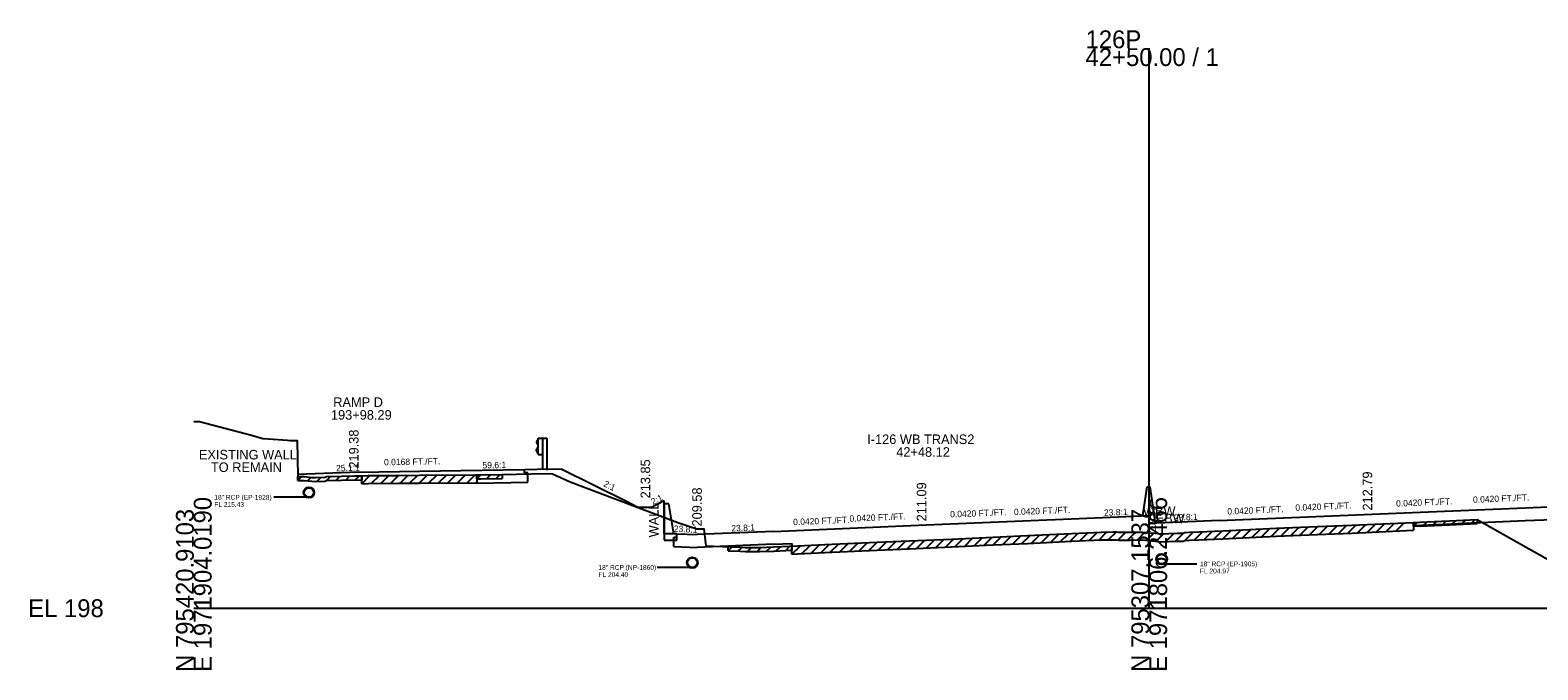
# Model space of a CAD drawing. Extents: x -161 to 1970889, y -4362 to 797231.
# Drawn here: x 974.3 to 1211, y 4990.3 to 5090.9 of the extents above; entities that cross this region are included whole.
import ezdxf

# ---------------------------------------------------------------- set-up
doc = ezdxf.new("R2010")
doc.units = 0
for name, color, linetype in [('RD_GPK_XS_Cell', 7, 'Continuous'), ('RD_XS_Base', 7, 'Continuous'), ('RD_XS_Box', 7, 'Continuous'), ('RD_XS_EarthShd', 7, 'Continuous'), ('RD_XS_ExGround', 7, 'Continuous'), ('RD_XS_ExPaveRet', 7, 'Continuous'), ('RD_XS_GR', 7, 'Continuous'), ('RD_XS_MedBWall', 7, 'Continuous'), ('RD_XS_Misc_Line', 7, 'Continuous'), ('RD_XS_Pave', 7, 'Continuous'), ('RD_XS_PaveOvlay', 7, 'Continuous'), ('RD_XS_PaveShd', 7, 'Continuous'), ('RD_XS_Pipe', 7, 'Continuous'), ('RD_XS_TieSlope', 7, 'Continuous'), ('RD_XS_TX_Elev_EX', 7, 'Continuous'), ('RD_XS_TX_Elev_PR', 7, 'Continuous'), ('RD_XS_TX_Misc', 7, 'Continuous'), ('RD_XS_TX_MkPT', 7, 'Continuous'), ('RD_XS_TX_Notes', 7, 'Continuous'), ('RD_XS_TX_Profile', 7, 'Continuous'), ('RD_XS_TX_Slope', 7, 'Continuous'), ('RD_XS_TX_Station', 7, 'Continuous')]:
    doc.layers.add(name, color=color, linetype=linetype)

msp = doc.modelspace()

# ---------------------------------------------------------------- linework, layer by layer
at = {"layer": 'RD_GPK_XS_Cell'}
for p, q in [((1150, 5000), (1150, 5088.01)), ((1000, 5000), (1150, 5000)), ((1150, 5000), (1300, 5000))]:
    msp.add_line(p, q, dxfattribs=at)
at = {"layer": 'RD_XS_Base'}
for p, q in [((1051.92, 5021.26), (1051.92, 5021.82)), ((1052.42, 5021.27), (1051.92, 5021.26)), ((1052.42, 5019.79), (1052.42, 5021.27)), ((1044.42, 5019.66), (1052.42, 5019.79)), ((1191.46, 5013.02), (1209, 5013.76)), ((1209, 5013.76), (1226.81, 5014.51)), ((1075.34, 5011.17), (1075.84, 5011.15)), ((1075.34, 5009.69), (1075.34, 5011.17)), ((1075.84, 5011.15), (1075.84, 5011.71)), ((1075.84, 5010.88), (1075.84, 5011.44)), ((1075.34, 5009.69), (1079, 5009.54)), ((1091, 5010.04), (1079, 5009.54)), ((1091, 5010.04), (1093.91, 5010.16))]:
    msp.add_line(p, q, dxfattribs=at)
at = {"layer": 'RD_XS_Box'}
for p, q in [((1073.84, 5011.71), (1073.84, 5016.85)), ((1075.84, 5011.71), (1073.84, 5011.71))]:
    msp.add_line(p, q, dxfattribs=at)
at = {"layer": 'RD_XS_EarthShd'}
msp.add_line((1051.92, 5021.82), (1053.92, 5021.85), dxfattribs=at)
at = {"layer": 'RD_XS_ExGround'}
msp.add_lwpolyline([(1000, 5029.34), (1000.89, 5029.32), (1009.06, 5027.22), (1010.83, 5026.67), (1011.72, 5026.61), (1014.7, 5026.39), (1015.05, 5026.36), (1016.23, 5026.36), (1016.33, 5020.71), (1017.35, 5020.68), (1018.54, 5020.56), (1019.1, 5020.52), (1020.57, 5020.6), (1020.84, 5020.71), (1023.18, 5020.75), (1027.35, 5020.83), (1032.16, 5020.88), (1035.44, 5020.92), (1044.22, 5020.94), (1044.53, 5020.95), (1045.07, 5020.95), (1048.43, 5020.99), (1050.65, 5021.04), (1055.38, 5021.15), (1056.3, 5021.14), (1059.11, 5019.86), (1076, 5013.48), (1078.98, 5012.47), (1079.42, 5012.47), (1080.05, 5012.47), (1080.38, 5009.8), (1081.6, 5009.75), (1085.79, 5009.57), (1086.56, 5009.53), (1087.24, 5009.54), (1088.79, 5009.55), (1091.05, 5009.62), (1094.82, 5009.79), (1099.05, 5010), (1107.21, 5010.38), (1112.31, 5010.59), (1118.93, 5010.87), (1125.49, 5011.19), (1130.89, 5011.44), (1137.81, 5011.76), (1142.47, 5011.97), (1144.31, 5011.99), (1144.85, 5012), (1145.18, 5011.93), (1146.94, 5011.95), (1148.94, 5011.97), (1150, 5011.87), (1150.96, 5011.79), (1151.71, 5011.7), (1154.4, 5011.77), (1155.35, 5011.78), (1155.59, 5011.91), (1156.34, 5011.95), (1157.77, 5012.01), (1161.5, 5012.17), (1169.96, 5012.56), (1176.35, 5012.82), (1181.79, 5013.05), (1191.43, 5013.49), (1193.57, 5013.59), (1197.14, 5013.74), (1201.46, 5013.93), (1209.2, 5009.59), (1223.35, 5001.64)], dxfattribs=at)
at = {"layer": 'RD_XS_ExPaveRet'}
for p, q in [((1016.33, 5020.08), (1016.33, 5020.71)), ((1026.36, 5019.56), (1026.36, 5020.81)), ((1026.36, 5020.81), (1026.36, 5020.19)), ((1044.42, 5020.95), (1044.42, 5019.7)), ((1044.42, 5020.32), (1044.42, 5020.95)), ((1048.43, 5020.99), (1048.43, 5020.36)), ((1016.33, 5020.08), (1017.35, 5020.06)), ((1017.35, 5020.06), (1018.54, 5019.94)), ((1018.54, 5019.94), (1019.1, 5019.89)), ((1019.1, 5019.89), (1020.57, 5019.97)), ((1020.57, 5019.97), (1020.84, 5020.08)), ((1020.84, 5020.08), (1023.18, 5020.12)), ((1023.18, 5020.12), (1026.36, 5020.19)), ((1026.36, 5019.56), (1027.35, 5019.58)), ((1027.35, 5019.58), (1032.16, 5019.63)), ((1032.16, 5019.63), (1035.44, 5019.67)), ((1035.44, 5019.67), (1044.22, 5019.69)), ((1044.22, 5019.69), (1044.42, 5019.7)), ((1044.42, 5020.32), (1044.53, 5020.32)), ((1044.53, 5020.32), (1045.07, 5020.33)), ((1045.07, 5020.33), (1048.43, 5020.36)), ((1191.46, 5013.49), (1191.46, 5012.24)), ((1191.46, 5012.87), (1191.46, 5013.49)), ((1201.46, 5013.93), (1201.46, 5013.3)), ((1161.5, 5010.92), (1169.96, 5011.31)), ((1169.96, 5011.31), (1176.35, 5011.57)), ((1176.35, 5011.57), (1181.79, 5011.8)), ((1181.79, 5011.8), (1191.43, 5012.24)), ((1191.43, 5012.24), (1191.46, 5012.24)), ((1191.46, 5012.87), (1193.57, 5012.96)), ((1193.57, 5012.96), (1197.14, 5013.11)), ((1197.14, 5013.11), (1201.46, 5013.3)), ((1083.91, 5009.03), (1083.91, 5009.65)), ((1083.91, 5009.03), (1085.79, 5008.95)), ((1085.79, 5008.95), (1086.56, 5008.91)), ((1086.56, 5008.91), (1087.24, 5008.92)), ((1087.24, 5008.92), (1088.79, 5008.92)), ((1088.79, 5008.92), (1091.05, 5008.99)), ((1091.05, 5008.99), (1093.91, 5009.12)), ((1093.91, 5008.5), (1093.91, 5009.75)), ((1093.91, 5009.75), (1093.91, 5009.12)), ((1094.82, 5008.54), (1099.05, 5008.75)), ((1099.05, 5008.75), (1107.21, 5009.13)), ((1107.21, 5009.13), (1112.31, 5009.34)), ((1112.31, 5009.34), (1118.93, 5009.62)), ((1118.93, 5009.62), (1125.49, 5009.94)), ((1125.49, 5009.94), (1130.89, 5010.19)), ((1130.89, 5010.19), (1137.81, 5010.51)), ((1137.81, 5010.51), (1142.47, 5010.72)), ((1142.47, 5010.72), (1144.31, 5010.74)), ((1144.31, 5010.74), (1144.85, 5010.75)), ((1144.85, 5010.75), (1145.18, 5010.68)), ((1145.18, 5010.68), (1146.94, 5010.7)), ((1146.94, 5010.7), (1148.94, 5010.72)), ((1148.94, 5010.72), (1150, 5010.62)), ((1150, 5010.62), (1150.96, 5010.54)), ((1150.96, 5010.54), (1151.71, 5010.45)), ((1151.71, 5010.45), (1154.4, 5010.52)), ((1154.4, 5010.52), (1155.35, 5010.53)), ((1155.35, 5010.53), (1155.59, 5010.66)), ((1155.59, 5010.66), (1156.34, 5010.7)), ((1156.34, 5010.7), (1157.77, 5010.76)), ((1157.77, 5010.76), (1161.5, 5010.92)), ((1093.91, 5008.5), (1094.82, 5008.54))]:
    msp.add_line(p, q, dxfattribs=at)
at = {"layer": 'RD_XS_GR'}
for p, q in [((1054.07, 5026.57), (1053.8, 5026.13)), ((1053.8, 5026.13), (1053.8, 5026.02)), ((1053.8, 5026.02), (1054.07, 5025.58)), ((1053.8, 5024.87), (1054.07, 5025.31)), ((1054.07, 5026.73), (1054.74, 5026.73)), ((1054.07, 5024.16), (1054.07, 5026.73)), ((1054.74, 5026.73), (1055.4, 5026.73)), ((1054.74, 5026.73), (1054.74, 5021.79)), ((1055.4, 5026.73), (1055.4, 5021.68)), ((1053.8, 5024.76), (1053.8, 5024.87)), ((1054.07, 5024.32), (1053.8, 5024.76)), ((1054.07, 5024.16), (1054.74, 5024.16))]:
    msp.add_line(p, q, dxfattribs=at)
at = {"layer": 'RD_XS_MedBWall'}
for p, q in [((1149, 5014.52), (1149.67, 5019.06)), ((1149.67, 5019.06), (1150.15, 5019.06)), ((1151, 5013.36), (1150.15, 5019.06)), ((1074.59, 5016.38), (1073.84, 5016.38)), ((1073.84, 5016.38), (1073.84, 5010.71)), ((1075.34, 5011.71), (1074.59, 5016.38)), ((1075.84, 5011.71), (1075.34, 5011.71)), ((1075.84, 5010.71), (1075.84, 5011.71)), ((1073.84, 5010.71), (1075.84, 5010.71))]:
    msp.add_line(p, q, dxfattribs=at)
at = {"layer": 'RD_XS_Misc_Line'}
for p, q in [((1016.33, 5020.08), (1016.94, 5020.69)), ((1017.83, 5020.01), (1018.4, 5020.58)), ((1019.34, 5019.9), (1020, 5020.57)), ((1020.84, 5020.08), (1021.48, 5020.72)), ((1022.34, 5020.11), (1022.98, 5020.75)), ((1023.85, 5020.14), (1024.49, 5020.78)), ((1025.35, 5020.17), (1025.99, 5020.81)), ((1026.36, 5019.56), (1027.63, 5020.84)), ((1027.86, 5019.59), (1029.13, 5020.85)), ((1029.37, 5019.6), (1030.63, 5020.86)), ((1030.87, 5019.62), (1032.14, 5020.88)), ((1032.38, 5019.63), (1033.65, 5020.9)), ((1033.88, 5019.65), (1035.15, 5020.92)), ((1035.38, 5019.67), (1036.64, 5020.93)), ((1036.89, 5019.68), (1038.15, 5020.93)), ((1038.39, 5019.68), (1039.65, 5020.93)), ((1039.9, 5019.68), (1041.15, 5020.94)), ((1041.4, 5019.69), (1042.66, 5020.94)), ((1042.91, 5019.69), (1044.16, 5020.94)), ((1044.42, 5020.32), (1045.06, 5020.95)), ((1045.93, 5020.34), (1046.56, 5020.97)), ((1047.43, 5020.35), (1048.07, 5020.98)), ((1187.2, 5012.05), (1188.51, 5013.36)), ((1188.7, 5012.12), (1190.02, 5013.43)), ((1191.46, 5012.87), (1192.11, 5013.52)), ((1192.96, 5012.94), (1193.62, 5013.59)), ((1194.47, 5013), (1195.12, 5013.65)), ((1195.97, 5013.07), (1196.62, 5013.72)), ((1197.47, 5013.13), (1198.13, 5013.78)), ((1198.98, 5013.19), (1199.63, 5013.85)), ((1200.48, 5013.26), (1201.14, 5013.91)), ((1119.49, 5009.65), (1120.81, 5010.96)), ((1121, 5009.72), (1122.31, 5011.04)), ((1122.5, 5009.79), (1123.82, 5011.11)), ((1124.01, 5009.87), (1125.32, 5011.18)), ((1125.51, 5009.94), (1126.83, 5011.25)), ((1127.01, 5010.01), (1128.33, 5011.32)), ((1128.52, 5010.08), (1129.83, 5011.39)), ((1130.02, 5010.15), (1131.34, 5011.46)), ((1131.53, 5010.22), (1132.84, 5011.53)), ((1133.03, 5010.29), (1134.35, 5011.6)), ((1134.54, 5010.36), (1135.85, 5011.67)), ((1136.04, 5010.42), (1137.36, 5011.74)), ((1137.55, 5010.49), (1138.86, 5011.8)), ((1139.05, 5010.56), (1140.37, 5011.87)), ((1140.56, 5010.63), (1141.87, 5011.94)), ((1142.06, 5010.7), (1143.34, 5011.98)), ((1143.57, 5010.73), (1144.84, 5012)), ((1145.07, 5010.7), (1146.31, 5011.94)), ((1146.57, 5010.7), (1147.84, 5011.96)), ((1148.08, 5010.71), (1149.31, 5011.93)), ((1149.58, 5010.66), (1150.74, 5011.81)), ((1151.09, 5010.53), (1152.28, 5011.72)), ((1152.59, 5010.47), (1153.88, 5011.75)), ((1154.1, 5010.51), (1155.4, 5011.81)), ((1155.6, 5010.66), (1156.92, 5011.97)), ((1157.11, 5010.73), (1158.42, 5012.04)), ((1158.61, 5010.8), (1159.92, 5012.1)), ((1160.12, 5010.86), (1161.43, 5012.17)), ((1161.62, 5010.93), (1162.93, 5012.24)), ((1163.13, 5011), (1164.44, 5012.31)), ((1164.63, 5011.06), (1165.94, 5012.37)), ((1166.13, 5011.13), (1167.45, 5012.44)), ((1167.64, 5011.2), (1168.95, 5012.51)), ((1169.14, 5011.27), (1170.46, 5012.58)), ((1170.65, 5011.34), (1171.96, 5012.64)), ((1172.15, 5011.4), (1173.46, 5012.7)), ((1173.66, 5011.46), (1174.97, 5012.77)), ((1175.16, 5011.52), (1176.47, 5012.83)), ((1176.67, 5011.59), (1177.98, 5012.89)), ((1178.17, 5011.65), (1179.48, 5012.95)), ((1179.68, 5011.71), (1180.98, 5013.02)), ((1181.18, 5011.77), (1182.49, 5013.08)), ((1182.69, 5011.84), (1184, 5013.15)), ((1184.19, 5011.91), (1185.5, 5013.22)), ((1185.7, 5011.98), (1187.01, 5013.29)), ((1083.91, 5009.03), (1084.51, 5009.63)), ((1085.42, 5008.96), (1086.02, 5009.56)), ((1086.92, 5008.91), (1087.55, 5009.54)), ((1088.42, 5008.92), (1089.06, 5009.56)), ((1089.93, 5008.96), (1090.58, 5009.6)), ((1091.43, 5009.01), (1092.09, 5009.67)), ((1092.94, 5009.08), (1093.59, 5009.73)), ((1093.91, 5008.5), (1095.23, 5009.81)), ((1095.42, 5008.57), (1096.74, 5009.88)), ((1096.92, 5008.64), (1098.24, 5009.96)), ((1098.43, 5008.72), (1099.74, 5010.03)), ((1099.93, 5008.79), (1101.25, 5010.1)), ((1101.44, 5008.86), (1102.75, 5010.17)), ((1102.94, 5008.93), (1104.26, 5010.24)), ((1104.45, 5009), (1105.76, 5010.31)), ((1105.95, 5009.07), (1107.27, 5010.38)), ((1107.45, 5009.14), (1108.76, 5010.44)), ((1108.96, 5009.2), (1110.27, 5010.51)), ((1110.46, 5009.27), (1111.77, 5010.57)), ((1111.97, 5009.33), (1113.28, 5010.64)), ((1113.47, 5009.39), (1114.78, 5010.7)), ((1114.98, 5009.46), (1116.29, 5010.76)), ((1116.48, 5009.52), (1117.79, 5010.83)), ((1117.99, 5009.58), (1119.3, 5010.89))]:
    msp.add_line(p, q, dxfattribs=at)
at = {"layer": 'RD_XS_Pave'}
for p, q in [((1025.86, 5021.38), (1041.9, 5021.65)), ((1185, 5014.79), (1209, 5015.8)), ((1115, 5013.09), (1139, 5014.1)), ((1161, 5013.78), (1185, 5014.79)), ((1091, 5012.08), (1115, 5013.09))]:
    msp.add_line(p, q, dxfattribs=at)
at = {"layer": 'RD_XS_PaveOvlay'}
for p, q in [((1026.36, 5020.81), (1027.35, 5020.83)), ((1027.35, 5020.83), (1032.16, 5020.88)), ((1032.16, 5020.88), (1035.44, 5020.92)), ((1035.44, 5020.92), (1044.22, 5020.94)), ((1044.22, 5020.94), (1044.42, 5020.95)), ((1044.42, 5020.95), (1044.42, 5019.66)), ((1181.79, 5013.05), (1191.43, 5013.49)), ((1191.43, 5013.49), (1191.46, 5013.49)), ((1191.46, 5013.49), (1191.46, 5013.02)), ((1118.93, 5010.87), (1125.49, 5011.19)), ((1125.49, 5011.19), (1130.89, 5011.44)), ((1130.89, 5011.44), (1137.81, 5011.76)), ((1137.81, 5011.76), (1142.47, 5011.97)), ((1142.47, 5011.97), (1144.31, 5011.99)), ((1144.31, 5011.99), (1144.85, 5012)), ((1144.85, 5012), (1145.18, 5011.93)), ((1145.18, 5011.93), (1146.94, 5011.95)), ((1146.94, 5011.95), (1148.94, 5011.97)), ((1148.94, 5011.97), (1150, 5011.87)), ((1150, 5011.87), (1150.96, 5011.79)), ((1150.96, 5011.79), (1151.71, 5011.7)), ((1151.71, 5011.7), (1154.4, 5011.77)), ((1154.4, 5011.77), (1155.35, 5011.78)), ((1155.35, 5011.78), (1155.59, 5011.91)), ((1155.59, 5011.91), (1156.34, 5011.95)), ((1156.34, 5011.95), (1157.77, 5012.01)), ((1157.77, 5012.01), (1161.5, 5012.17)), ((1161.5, 5012.17), (1169.96, 5012.56)), ((1169.96, 5012.56), (1176.35, 5012.82)), ((1176.35, 5012.82), (1181.79, 5013.05)), ((1093.91, 5010.16), (1093.91, 5009.75)), ((1093.91, 5009.75), (1094.82, 5009.79)), ((1094.82, 5009.79), (1099.05, 5010)), ((1099.05, 5010), (1107.21, 5010.38)), ((1107.21, 5010.38), (1112.31, 5010.59)), ((1112.31, 5010.59), (1118.93, 5010.87))]:
    msp.add_line(p, q, dxfattribs=at)
msp.add_lwpolyline([(1016.32, 5021), (1016.33, 5020.71), (1017.35, 5020.68), (1018.54, 5020.56), (1019.1, 5020.52), (1020.57, 5020.6), (1020.84, 5020.71), (1023.18, 5020.75), (1026.36, 5020.81)], dxfattribs=at)
at = {"layer": 'RD_XS_PaveShd'}
for p, q in [((1025.86, 5021.38), (1016.32, 5021)), ((1041.9, 5021.65), (1051.92, 5021.82)), ((1209, 5015.8), (1226.84, 5016.55)), ((1139, 5014.1), (1150, 5014.56)), ((1150, 5013.32), (1150, 5014.56)), ((1161, 5013.78), (1150, 5013.32)), ((1075.84, 5011.71), (1079, 5011.58)), ((1091, 5012.08), (1079, 5011.58))]:
    msp.add_line(p, q, dxfattribs=at)
at = {"layer": 'RD_XS_Pipe'}
for p, q in [((1017.57, 5017.43), (1012.57, 5017.43)), ((1077.76, 5006.4), (1072.76, 5006.4)), ((1152.46, 5006.97), (1157.46, 5006.97))]:
    msp.add_line(p, q, dxfattribs=at)
for centre, radius in [((1018.07, 5018.18), 0.85), ((1018.07, 5018.18), 0.75), ((1078.26, 5007.15), 0.85), ((1078.26, 5007.15), 0.75), ((1151.96, 5007.72), 0.85), ((1151.96, 5007.72), 0.75)]:
    msp.add_circle(centre, radius, dxfattribs=at)
at = {"layer": 'RD_XS_TieSlope'}
for p, q in [((1053.92, 5021.85), (1057.68, 5021.92)), ((1057.68, 5021.92), (1067.84, 5016.85)), ((1067.84, 5016.85), (1069.84, 5015.85)), ((1071.84, 5015.85), (1069.84, 5015.85)), ((1073.84, 5016.85), (1071.84, 5015.85))]:
    msp.add_line(p, q, dxfattribs=at)

# ---------------------------------------------------------------- texts
at = {"layer": 'RD_GPK_XS_Cell'}
for s, p in [('126P', (1140, 5088.01)), ('42+50.00 / 1', (1140, 5085.21)), ('EL 198', (974, 4998.6))]:
    msp.add_text(s, height=2.8, dxfattribs=at).set_placement(p)
for s, p in [('E 1971904.0190', (1002.8, 4990)), ('E 1971806.2466', (1152.8, 4990)), ('N 795420.9103', (1000, 4990)), ('N 795307.1537', (1150, 4990))]:
    msp.add_text(s, height=2.8, rotation=90, dxfattribs=at).set_placement(p)
at = {"layer": 'RD_XS_Pipe'}
for s, p in [('18" RCP (EP-1928)', (1003.22, 5017.06)), ('FL 215.43', (1003.22, 5015.93)), ('18" RCP (NP-1860)', (1063.53, 5006.03)), ('18" RCP (EP-1905)', (1157.96, 5006.59)), ('FL 204.97', (1157.96, 5005.47)), ('FL 204.40', (1063.53, 5004.9))]:
    msp.add_text(s, height=0.75, dxfattribs=at).set_placement(p)
at = {"layer": 'RD_XS_TX_Elev_EX'}
msp.add_text('209.87', height=1, rotation=90, dxfattribs=at).set_placement((1151, 5011.87))
at = {"layer": 'RD_XS_TX_Elev_PR'}
for s, p in [(' 219.38', (1025.86, 5021.38)), (' 212.79', (1185, 5014.79)), (' 211.09', (1115, 5013.09))]:
    msp.add_text(s, height=1.5, rotation=90, dxfattribs=at).set_placement(p)
at = {"layer": 'RD_XS_TX_Misc'}
for s, p in [('213.85', (1071.65, 5017.26)), ('209.58', (1079.75, 5012.84))]:
    msp.add_text(s, height=1.5, rotation=90, dxfattribs=at).set_placement(p)
at = {"layer": 'RD_XS_TX_MkPT'}
for s, p in [('WBW', (1149, 5014.52)), ('EBW', (1151, 5013.36))]:
    msp.add_text(s, height=1.5, dxfattribs=at).set_placement(p)
at = {"layer": 'RD_XS_TX_Notes'}
for s, p in [('EXISTING WALL', (1000.8, 5023.38)), ('TO REMAIN', (1002.69, 5021.41))]:
    msp.add_text(s, height=1.5, dxfattribs=at).set_placement(p)
msp.add_text('WALL', height=1.5, rotation=90, dxfattribs=at).set_placement((1072.96, 5011.14))
at = {"layer": 'RD_XS_TX_Profile'}
for s, rotation, p in [('59.6:1', 0.9605, (1045.33, 5021.96)), ('23.8:1', 2.405, (1142.91, 5014.51)), ('23.8:1', 2.405, (1153.91, 5013.74)), ('23.8:1', 357.595, (1075.34, 5012.01)), ('23.8:1', 2.405, (1084.41, 5012.05))]:
    msp.add_text(s, height=1, rotation=rotation, dxfattribs=at).set_placement(p)
at = {"layer": 'RD_XS_TX_Slope'}
for s, rotation, p in [('0.0168 FT./FT.', 0.9605, (1029.87, 5022.45)), ('25.1:1', 2.2853, (1022.36, 5021.49)), ('2:1', 333.4883, (1064.21, 5019.22)), ('2:1', 26.5651, (1072.08, 5016.21)), ('0.0420 FT./FT.', 2.405, (1128.77, 5014.62)), ('0.0420 FT./FT.', 2.405, (1162.28, 5014.71)), ('0.0420 FT./FT.', 2.405, (1172.96, 5015.29)), ('0.0420 FT./FT.', 2.405, (1188.77, 5015.95)), ('0.0420 FT./FT.', 2.405, (1200.85, 5016.55)), ('0.0420 FT./FT.', 2.405, (1094.11, 5013.04)), ('0.0420 FT./FT.', 2.405, (1102.96, 5013.58)), ('0.0420 FT./FT.', 2.405, (1118.77, 5014.25))]:
    msp.add_text(s, height=1, rotation=rotation, dxfattribs=at).set_placement(p)
at = {"layer": 'RD_XS_TX_Station'}
for s, p in [('RAMP D', (1021.89, 5031.63)), ('193+98.29', (1021.53, 5029.63)), ('I-126 WB TRANS2', (1105.72, 5025.8)), ('42+48.12', (1110.28, 5023.8))]:
    msp.add_text(s, height=1.5, dxfattribs=at).set_placement(p)

doc.saveas('drawing.dxf')
